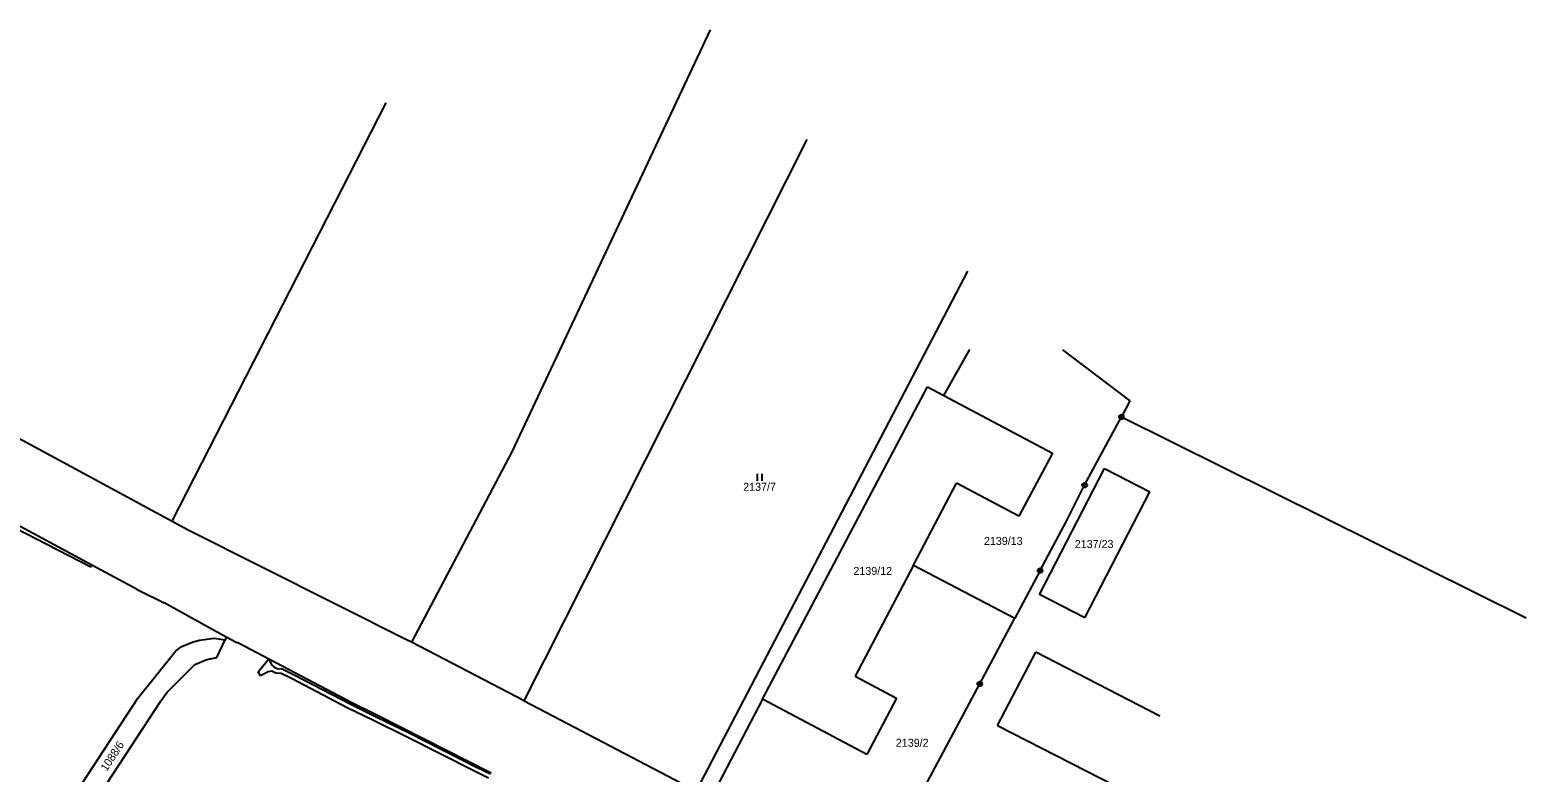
# Model space of a CAD drawing. Extents: x -621172 to -616925, y -1123899 to -1119548.
# Drawn here: x -619154.3 to -618836.5, y -1121405.1 to -1121247.5 of the extents above; entities that cross this region are included whole.
import ezdxf

# ---------------------------------------------------------------- set-up
doc = ezdxf.new("R2010")
doc.units = 0
for name, color, linetype in [('Vrstva 1', 7, 'Continuous'), ('Vrstva 18', 7, 'Continuous'), ('Vrstva 19', 7, 'Continuous'), ('Vrstva 24', 7, 'Continuous'), ('Vrstva 25', 7, 'Continuous')]:
    doc.layers.add(name, color=color, linetype=linetype)

msp = doc.modelspace()

# ---------------------------------------------------------------- linework, layer by layer
at = {"layer": 'Vrstva 1'}
for points in [[(-619009.82, -1121247.52), (-619051.92, -1121337.08)], [(-619124.1, -1121351.82), (-619078.6, -1121262.97)], [(-619049.34, -1121389.99), (-618989.2, -1121270.79)], [(-618955.1, -1121298.75), (-619012.8, -1121409.09)], [(-619191.16, -1121315.58), (-619124.1, -1121351.82)], [(-618960.13, -1121325.17), (-618954.6, -1121315.41)], [(-618934.94, -1121315.47), (-618920.61, -1121326.29)], [(-618998.66, -1121389.66), (-618963.65, -1121323.31)], [(-618963.65, -1121323.31), (-618960.13, -1121325.17)], [(-618960.13, -1121325.17), (-618937.08, -1121337.36)], [(-618920.61, -1121326.29), (-618922.43, -1121329.68)], [(-618930.23, -1121344.2), (-618922.43, -1121329.68)], [(-618922.43, -1121329.68), (-618836.45, -1121372.37)], [(-619141.38, -1121361.62), (-619190.24, -1121336.5)], [(-619051.92, -1121337.08), (-619073.23, -1121377.51)], [(-618937.08, -1121337.36), (-618944.22, -1121350.8)], [(-618939.8, -1121367.44), (-618925.99, -1121340.67)], [(-618925.99, -1121340.67), (-618916.42, -1121345.6)], [(-618966.63, -1121361.18), (-618957.48, -1121343.79)], [(-618944.22, -1121350.8), (-618957.48, -1121343.79)], [(-618934.07, -1121351.81), (-618930.23, -1121344.2)], [(-618930.17, -1121372.37), (-618916.42, -1121345.6)], [(-619141.15, -1121361.2), (-619159.77, -1121351.16)], [(-619124.1, -1121351.82), (-619120.81, -1121353.6)], [(-619120.81, -1121353.6), (-619073.73, -1121377.25)], [(-618939.69, -1121362.33), (-618934.07, -1121351.81)], [(-619141.15, -1121361.2), (-619141.38, -1121361.62)], [(-619131.55, -1121366.37), (-619141.15, -1121361.2)], [(-618966.63, -1121361.18), (-618979.02, -1121384.74)], [(-618966.63, -1121361.18), (-618945.1, -1121372.46)], [(-618939.69, -1121362.33), (-618945.1, -1121372.46)], [(-619131.55, -1121366.37), (-619125.81, -1121369.2)], [(-619112.59, -1121376.47), (-619125.81, -1121369.2)], [(-618930.17, -1121372.37), (-618939.8, -1121367.44)], [(-618952.52, -1121386.38), (-618945.1, -1121372.46)], [(-619118.31, -1121377.13), (-619115.18, -1121376.7)], [(-619115.18, -1121376.7), (-619112.84, -1121377.02)], [(-619112.59, -1121376.47), (-619112.84, -1121377.02)], [(-619110.36, -1121377.66), (-619112.59, -1121376.47)], [(-619131.38, -1121389.44), (-619123.35, -1121379.4)], [(-619123.35, -1121379.4), (-619122.02, -1121378.46)], [(-619122.02, -1121378.46), (-619119.62, -1121377.48)], [(-619119.62, -1121377.48), (-619118.31, -1121377.13)], [(-619114.58, -1121380.78), (-619112.84, -1121377.02)], [(-619109.98, -1121377.7), (-619110.36, -1121377.66)], [(-619109.98, -1121377.7), (-619086.04, -1121390.3)], [(-619073.23, -1121377.51), (-619073.73, -1121377.25)], [(-619049.34, -1121389.99), (-619073.23, -1121377.51)], [(-618948.77, -1121395.2), (-618940.62, -1121379.67)], [(-618914.23, -1121393.21), (-618940.62, -1121379.67)], [(-619125.15, -1121388.12), (-619119.29, -1121382.26)], [(-619119.29, -1121382.26), (-619116.75, -1121381.21)], [(-619116.75, -1121381.21), (-619114.58, -1121380.78)], [(-619105.79, -1121383.83), (-619103.58, -1121381.07)], [(-619103.58, -1121381.07), (-619103, -1121382.34)], [(-619103, -1121382.34), (-619102.5, -1121382.8)], [(-619102.5, -1121382.8), (-619101.8, -1121383.12)], [(-619101.8, -1121383.12), (-619100.7, -1121383.2)], [(-619100.7, -1121383.2), (-619098.17, -1121384.44)], [(-619105.32, -1121384.68), (-619105.79, -1121383.83)], [(-619103.71, -1121383.8), (-619105.32, -1121384.68)], [(-619102.92, -1121383.7), (-619103.71, -1121383.8)], [(-619102.06, -1121384.1), (-619102.92, -1121383.7)], [(-619100.96, -1121384.18), (-619102.06, -1121384.1)], [(-619098.63, -1121385.34), (-619100.96, -1121384.18)], [(-619086.93, -1121391.44), (-619098.63, -1121385.34)], [(-619098.17, -1121384.44), (-619086.3, -1121390.64)], [(-618979.02, -1121384.74), (-618970.18, -1121389.39)], [(-618974.68, -1121427.88), (-618952.52, -1121386.38)], [(-619154.13, -1121424.18), (-619131.38, -1121389.44)], [(-619126.66, -1121390.22), (-619125.15, -1121388.12)], [(-618970.18, -1121389.39), (-618976.51, -1121401.35)], [(-619126.66, -1121390.22), (-619150.5, -1121426.64)], [(-619081.31, -1121394.19), (-619086.93, -1121391.44)], [(-619086.3, -1121390.64), (-619080.72, -1121393.37)], [(-619086.04, -1121390.3), (-619080.47, -1121393.03)], [(-619049.34, -1121389.99), (-619012.8, -1121409.09)], [(-618998.66, -1121389.66), (-619008.81, -1121409.03)], [(-618976.51, -1121401.35), (-618998.66, -1121389.66)], [(-619074.16, -1121397.69), (-619081.31, -1121394.19)], [(-619080.72, -1121393.37), (-619073.72, -1121396.79)], [(-619080.47, -1121393.03), (-619056.33, -1121405.28)], [(-618948.77, -1121395.2), (-618892.53, -1121423.98)], [(-619060.03, -1121404.87), (-619074.16, -1121397.69)], [(-619073.72, -1121396.79), (-619059.59, -1121403.97)], [(-619056.87, -1121406.43), (-619060.03, -1121404.87)], [(-619059.59, -1121403.97), (-619056.44, -1121405.52)]]:
    msp.add_lwpolyline(points, dxfattribs=at)
at = {"layer": 'Vrstva 24'}
for centre, radius in [((-618922.43, -1121329.68), 0.5), ((-618922.43, -1121329.68), 0.1), ((-618930.23, -1121344.2), 0.5), ((-618930.23, -1121344.2), 0.1), ((-618939.69, -1121362.33), 0.5), ((-618939.69, -1121362.33), 0.1), ((-618952.52, -1121386.38), 0.5), ((-618952.52, -1121386.38), 0.1)]:
    msp.add_circle(centre, radius, dxfattribs=at)
at = {"layer": 'Vrstva 25'}
for p, q in [((-618999.728, -1121343.256), (-618999.728, -1121341.756)), ((-618998.728, -1121343.256), (-618998.728, -1121341.756))]:
    msp.add_line(p, q, dxfattribs=at)

# ---------------------------------------------------------------- texts
at = {"layer": 'Vrstva 18'}
for s, p in [('2137/7', (-619002.781, -1121345.39)), ('2139/13', (-618951.63, -1121356.88)), ('2139/2', (-618970.347, -1121399.74))]:
    msp.add_text(s, height=1.7, dxfattribs=at).set_placement(p)
msp.add_text('1088/6', height=1.7, rotation=56.7, dxfattribs=at).set_placement((-619138.02, -1121405.09))
at = {"layer": 'Vrstva 19'}
for s, p in [('2137/23', (-618932.327, -1121357.54)), ('2139/12', (-618979.358, -1121363.25))]:
    msp.add_text(s, height=1.7, dxfattribs=at).set_placement(p)

doc.saveas('drawing.dxf')
